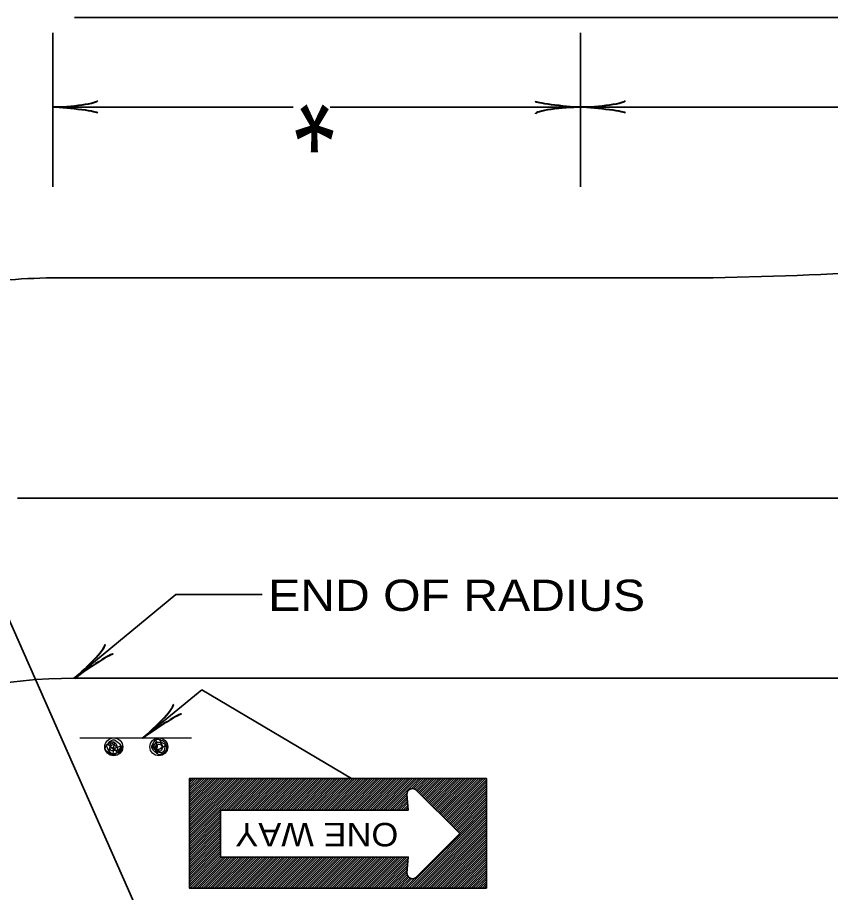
# Model space of a CAD drawing. Extents: x 1081 to 1936, y -630 to -24.
# Drawn here: x 1768.1 to 1830.4, y -254.8 to -187.6 of the extents above; entities that cross this region are included whole.
import ezdxf
from ezdxf.enums import TextEntityAlignment as Align

# ---------------------------------------------------------------- set-up
doc = ezdxf.new("R2010")
doc.units = 0
doc.layers.add('1', color=7, linetype='Continuous', lineweight=53)
doc.layers.add('4', color=7, linetype='Continuous', lineweight=25)

msp = doc.modelspace()

# ---------------------------------------------------------------- linework, layer by layer
at = {"layer": '1', "lineweight": 35}
for p, q in [((1772.44, -187.636), (1910.312, -187.636)), ((1770.768, -188.815), (1770.768, -200.637)), ((1811.244, -188.815), (1811.244, -200.637)), ((1789.206, -194.511), (1770.768, -194.511)), ((1811.244, -194.511), (1792.054, -194.511)), ((1892.659, -194.511), (1811.244, -194.511)), ((1754.117, -203.748), (1782.36, -267.638)), ((1771.98, -207.606), (1771.653, -207.606)), ((1821.432, -207.604), (1771.659, -207.604)), ((1826.968, -207.46), (1821.432, -207.604)), ((1772.978, -224.502), (1768.069, -224.502)), ((1910.312, -224.5), (1771.659, -224.5)), ((1780.221, -231.901), (1772.44, -238.324)), ((1780.221, -231.901), (1786.847, -231.901)), ((1772.44, -238.324), (1910.312, -238.324)), ((1782.205, -239.203), (1777.673, -242.919)), ((1782.205, -239.203), (1793.696, -246.024)), ((1785.974, -246.024), (1781.25, -250.749)), ((1785.805, -246.024), (1781.25, -250.579)), ((1785.635, -246.024), (1781.25, -250.409)), ((1785.465, -246.024), (1781.25, -250.239)), ((1785.296, -246.024), (1781.25, -250.07)), ((1785.126, -246.024), (1781.25, -249.9)), ((1784.956, -246.024), (1781.25, -249.73)), ((1784.786, -246.024), (1781.25, -249.561)), ((1784.617, -246.024), (1781.25, -249.391)), ((1784.447, -246.024), (1781.25, -249.221)), ((1784.277, -246.024), (1781.25, -249.052)), ((1784.108, -246.024), (1781.25, -248.882)), ((1783.938, -246.024), (1781.25, -248.712)), ((1783.768, -246.024), (1781.25, -248.542)), ((1783.599, -246.024), (1781.25, -248.373)), ((1783.429, -246.024), (1781.25, -248.203)), ((1783.259, -246.024), (1781.25, -248.033)), ((1783.089, -246.024), (1781.25, -247.864)), ((1782.92, -246.024), (1781.25, -247.694)), ((1782.75, -246.024), (1781.25, -247.524)), ((1782.58, -246.024), (1781.25, -247.354)), ((1782.411, -246.024), (1781.25, -247.185)), ((1782.241, -246.024), (1781.25, -247.015)), ((1782.071, -246.024), (1781.25, -246.845)), ((1781.901, -246.024), (1781.25, -246.676)), ((1781.732, -246.024), (1781.25, -246.506)), ((1781.562, -246.024), (1781.25, -246.336)), ((1781.392, -246.024), (1781.25, -246.167)), ((1786.144, -246.024), (1783.722, -248.446)), ((1786.314, -246.024), (1783.892, -248.446)), ((1786.484, -246.024), (1784.062, -248.446)), ((1786.653, -246.024), (1784.231, -248.446)), ((1786.823, -246.024), (1784.401, -248.446)), ((1786.993, -246.024), (1784.571, -248.446)), ((1787.162, -246.024), (1784.74, -248.446)), ((1787.332, -246.024), (1784.91, -248.446)), ((1787.502, -246.024), (1785.08, -248.446)), ((1787.671, -246.024), (1785.25, -248.446)), ((1787.841, -246.024), (1785.419, -248.446)), ((1788.011, -246.024), (1785.589, -248.446)), ((1788.181, -246.024), (1785.759, -248.446)), ((1788.35, -246.024), (1785.928, -248.446)), ((1788.52, -246.024), (1786.098, -248.446)), ((1788.69, -246.024), (1786.268, -248.446)), ((1788.859, -246.024), (1786.438, -248.446)), ((1789.029, -246.024), (1786.607, -248.446)), ((1789.199, -246.024), (1786.777, -248.446)), ((1789.369, -246.024), (1786.947, -248.446)), ((1789.538, -246.024), (1787.116, -248.446)), ((1789.708, -246.024), (1787.286, -248.446)), ((1789.878, -246.024), (1787.456, -248.446)), ((1790.047, -246.024), (1787.625, -248.446)), ((1790.217, -246.024), (1787.795, -248.446)), ((1790.387, -246.024), (1787.965, -248.446)), ((1790.556, -246.024), (1788.135, -248.446)), ((1790.726, -246.024), (1788.304, -248.446)), ((1790.896, -246.024), (1788.474, -248.446)), ((1791.066, -246.024), (1788.644, -248.446)), ((1791.235, -246.024), (1788.813, -248.446)), ((1791.405, -246.024), (1788.983, -248.446)), ((1791.575, -246.024), (1789.153, -248.446)), ((1791.744, -246.024), (1789.322, -248.446)), ((1791.914, -246.024), (1789.492, -248.446)), ((1792.084, -246.024), (1789.662, -248.446)), ((1792.254, -246.024), (1789.832, -248.446)), ((1792.423, -246.024), (1790.001, -248.446)), ((1792.593, -246.024), (1790.171, -248.446)), ((1792.763, -246.024), (1790.341, -248.446)), ((1792.932, -246.024), (1790.51, -248.446)), ((1793.102, -246.024), (1790.68, -248.446)), ((1793.272, -246.024), (1790.85, -248.446)), ((1793.441, -246.024), (1791.02, -248.446)), ((1793.611, -246.024), (1791.189, -248.446)), ((1793.781, -246.024), (1791.359, -248.446)), ((1793.951, -246.024), (1791.529, -248.446)), ((1794.12, -246.024), (1791.698, -248.446)), ((1794.29, -246.024), (1791.868, -248.446)), ((1794.46, -246.024), (1792.038, -248.446)), ((1794.629, -246.024), (1792.207, -248.446)), ((1794.799, -246.024), (1792.377, -248.446)), ((1794.969, -246.024), (1792.547, -248.446)), ((1795.139, -246.024), (1792.717, -248.446)), ((1795.308, -246.024), (1792.886, -248.446)), ((1795.478, -246.024), (1793.056, -248.446)), ((1795.648, -246.024), (1793.226, -248.446)), ((1795.817, -246.024), (1793.395, -248.446)), ((1795.987, -246.024), (1793.565, -248.446)), ((1796.157, -246.024), (1793.735, -248.446)), ((1796.326, -246.024), (1793.905, -248.446)), ((1796.496, -246.024), (1794.074, -248.446)), ((1796.666, -246.024), (1794.244, -248.446)), ((1796.836, -246.024), (1794.414, -248.446)), ((1797.005, -246.024), (1794.583, -248.446)), ((1797.175, -246.024), (1794.753, -248.446)), ((1797.345, -246.024), (1794.923, -248.446)), ((1797.514, -246.024), (1795.092, -248.446)), ((1797.684, -246.024), (1795.262, -248.446)), ((1797.854, -246.024), (1795.432, -248.446)), ((1798.024, -246.024), (1795.602, -248.446)), ((1798.193, -246.024), (1795.771, -248.446)), ((1798.363, -246.024), (1795.941, -248.446)), ((1798.533, -246.024), (1796.111, -248.446)), ((1798.702, -246.024), (1796.28, -248.446)), ((1798.872, -246.024), (1796.45, -248.446)), ((1799.042, -246.024), (1798.264, -246.802)), ((1799.211, -246.024), (1798.441, -246.795)), ((1799.381, -246.024), (1798.569, -246.837)), ((1799.551, -246.024), (1798.66, -246.916)), ((1799.721, -246.024), (1798.745, -247)), ((1799.89, -246.024), (1798.829, -247.085)), ((1800.06, -246.024), (1798.914, -247.17)), ((1800.23, -246.024), (1798.999, -247.255)), ((1800.399, -246.024), (1799.084, -247.34)), ((1800.569, -246.024), (1799.169, -247.425)), ((1800.739, -246.024), (1799.254, -247.509)), ((1800.909, -246.024), (1799.339, -247.594)), ((1801.078, -246.024), (1799.423, -247.679)), ((1801.248, -246.024), (1799.508, -247.764)), ((1801.418, -246.024), (1799.593, -247.849)), ((1801.587, -246.024), (1799.678, -247.934)), ((1801.757, -246.024), (1799.763, -248.019)), ((1801.927, -246.024), (1799.848, -248.103)), ((1802.096, -246.024), (1799.932, -248.188)), ((1802.266, -246.024), (1800.017, -248.273)), ((1802.436, -246.024), (1800.102, -248.358)), ((1802.606, -246.024), (1800.187, -248.443)), ((1802.775, -246.024), (1800.272, -248.528)), ((1802.945, -246.024), (1800.357, -248.613)), ((1803.115, -246.024), (1800.442, -248.697)), ((1803.284, -246.024), (1800.526, -248.782)), ((1803.454, -246.024), (1800.611, -248.867)), ((1803.624, -246.024), (1800.696, -248.952)), ((1803.793, -246.024), (1800.781, -249.037)), ((1803.963, -246.024), (1800.866, -249.122)), ((1804.05, -246.107), (1800.951, -249.207)), ((1804.05, -246.277), (1801.036, -249.291)), ((1798.596, -246.852), (1801.99, -250.246)), ((1804.05, -246.447), (1801.12, -249.376)), ((1804.05, -246.616), (1801.205, -249.461)), ((1804.05, -246.786), (1801.29, -249.546)), ((1804.05, -246.956), (1801.375, -249.631)), ((1797.947, -247.119), (1796.62, -248.446)), ((1797.938, -247.297), (1796.79, -248.446)), ((1797.952, -247.453), (1796.959, -248.446)), ((1797.966, -247.609), (1797.129, -248.446)), ((1804.05, -247.125), (1801.46, -249.716)), ((1804.05, -247.295), (1801.545, -249.8)), ((1804.05, -247.465), (1801.63, -249.885)), ((1804.05, -247.634), (1801.714, -249.97)), ((1797.979, -247.766), (1797.299, -248.446)), ((1797.993, -247.922), (1797.468, -248.446)), ((1798.007, -248.078), (1797.638, -248.446)), ((1798.02, -248.234), (1797.808, -248.446)), ((1804.05, -248.313), (1797.939, -254.424)), ((1804.05, -247.804), (1801.799, -250.055)), ((1804.05, -247.974), (1801.884, -250.14)), ((1804.05, -248.144), (1801.969, -250.225)), ((1783.639, -248.53), (1781.25, -250.918)), ((1783.639, -248.699), (1781.25, -251.088)), ((1783.639, -248.869), (1781.25, -251.258)), ((1783.639, -249.039), (1781.25, -251.427)), ((1798.034, -248.39), (1797.977, -248.446)), ((1804.05, -248.483), (1798.109, -254.424)), ((1804.05, -248.653), (1798.278, -254.424)), ((1804.05, -248.822), (1798.448, -254.424)), ((1804.05, -248.992), (1798.618, -254.424)), ((1783.639, -249.208), (1781.25, -251.597)), ((1783.639, -249.378), (1781.25, -251.767)), ((1783.639, -249.548), (1781.25, -251.937)), ((1804.05, -249.162), (1798.788, -254.424)), ((1804.05, -249.332), (1798.957, -254.424)), ((1804.05, -249.501), (1799.127, -254.424)), ((1804.05, -249.671), (1799.297, -254.424)), ((1783.639, -249.717), (1781.25, -252.106)), ((1783.639, -249.887), (1781.25, -252.276)), ((1783.639, -250.057), (1781.25, -252.446)), ((1783.639, -250.227), (1781.25, -252.615)), ((1801.99, -250.246), (1798.596, -253.64)), ((1804.05, -249.841), (1799.466, -254.424)), ((1804.05, -250.01), (1799.636, -254.424)), ((1804.05, -250.18), (1799.806, -254.424)), ((1804.05, -250.35), (1799.976, -254.424)), ((1783.639, -250.396), (1781.25, -252.785)), ((1783.639, -250.566), (1781.25, -252.955)), ((1783.639, -250.736), (1781.25, -253.124)), ((1783.639, -250.905), (1781.25, -253.294)), ((1804.05, -250.519), (1800.145, -254.424)), ((1804.05, -250.689), (1800.315, -254.424)), ((1804.05, -250.859), (1800.485, -254.424)), ((1804.05, -251.029), (1800.654, -254.424)), ((1783.639, -251.075), (1781.25, -253.464)), ((1783.639, -251.245), (1781.25, -253.634)), ((1783.639, -251.415), (1781.25, -253.803)), ((1783.639, -251.584), (1781.25, -253.973)), ((1804.05, -251.198), (1800.824, -254.424)), ((1804.05, -251.368), (1800.994, -254.424)), ((1804.05, -251.538), (1801.163, -254.424)), ((1804.05, -251.707), (1801.333, -254.424)), ((1783.639, -251.754), (1781.25, -254.143)), ((1783.639, -251.924), (1781.25, -254.312)), ((1783.686, -252.046), (1781.308, -254.424)), ((1783.856, -252.046), (1781.478, -254.424)), ((1784.025, -252.046), (1781.647, -254.424)), ((1784.195, -252.046), (1781.817, -254.424)), ((1784.365, -252.046), (1781.987, -254.424)), ((1784.534, -252.046), (1782.156, -254.424)), ((1784.704, -252.046), (1782.326, -254.424)), ((1784.874, -252.046), (1782.496, -254.424)), ((1785.044, -252.046), (1782.666, -254.424)), ((1785.213, -252.046), (1782.835, -254.424)), ((1785.383, -252.046), (1783.005, -254.424)), ((1785.553, -252.046), (1783.175, -254.424)), ((1785.723, -252.046), (1783.344, -254.424)), ((1785.892, -252.046), (1783.514, -254.424)), ((1786.062, -252.046), (1783.684, -254.424)), ((1786.232, -252.046), (1783.854, -254.424)), ((1786.401, -252.046), (1784.023, -254.424)), ((1786.571, -252.046), (1784.193, -254.424)), ((1786.741, -252.046), (1784.363, -254.424)), ((1786.91, -252.046), (1784.532, -254.424)), ((1787.08, -252.046), (1784.702, -254.424)), ((1787.25, -252.046), (1784.872, -254.424)), ((1787.42, -252.046), (1785.041, -254.424)), ((1787.589, -252.046), (1785.211, -254.424)), ((1787.759, -252.046), (1785.381, -254.424)), ((1787.929, -252.046), (1785.551, -254.424)), ((1788.098, -252.046), (1785.72, -254.424)), ((1788.268, -252.046), (1785.89, -254.424)), ((1788.438, -252.046), (1786.06, -254.424)), ((1788.607, -252.046), (1786.229, -254.424)), ((1788.777, -252.046), (1786.399, -254.424)), ((1788.947, -252.046), (1786.569, -254.424)), ((1789.117, -252.046), (1786.739, -254.424)), ((1789.286, -252.046), (1786.908, -254.424)), ((1789.456, -252.046), (1787.078, -254.424)), ((1789.626, -252.046), (1787.248, -254.424)), ((1789.795, -252.046), (1787.417, -254.424)), ((1789.965, -252.046), (1787.587, -254.424)), ((1790.135, -252.046), (1787.757, -254.424)), ((1790.305, -252.046), (1787.926, -254.424)), ((1790.474, -252.046), (1788.096, -254.424)), ((1790.644, -252.046), (1788.266, -254.424)), ((1790.814, -252.046), (1788.436, -254.424)), ((1790.983, -252.046), (1788.605, -254.424)), ((1791.153, -252.046), (1788.775, -254.424)), ((1791.323, -252.046), (1788.945, -254.424)), ((1791.492, -252.046), (1789.114, -254.424)), ((1791.662, -252.046), (1789.284, -254.424)), ((1791.832, -252.046), (1789.454, -254.424)), ((1792.002, -252.046), (1789.624, -254.424)), ((1792.171, -252.046), (1789.793, -254.424)), ((1792.341, -252.046), (1789.963, -254.424)), ((1792.511, -252.046), (1790.133, -254.424)), ((1792.68, -252.046), (1790.302, -254.424)), ((1792.85, -252.046), (1790.472, -254.424)), ((1793.02, -252.046), (1790.642, -254.424)), ((1793.19, -252.046), (1790.811, -254.424)), ((1793.359, -252.046), (1790.981, -254.424)), ((1793.529, -252.046), (1791.151, -254.424)), ((1793.699, -252.046), (1791.321, -254.424)), ((1793.868, -252.046), (1791.49, -254.424)), ((1794.038, -252.046), (1791.66, -254.424)), ((1794.208, -252.046), (1791.83, -254.424)), ((1794.377, -252.046), (1791.999, -254.424)), ((1794.547, -252.046), (1792.169, -254.424)), ((1794.717, -252.046), (1792.339, -254.424)), ((1794.887, -252.046), (1792.509, -254.424)), ((1795.056, -252.046), (1792.678, -254.424)), ((1795.226, -252.046), (1792.848, -254.424)), ((1795.396, -252.046), (1793.018, -254.424)), ((1795.565, -252.046), (1793.187, -254.424)), ((1795.735, -252.046), (1793.357, -254.424)), ((1795.905, -252.046), (1793.527, -254.424)), ((1796.075, -252.046), (1793.696, -254.424)), ((1796.244, -252.046), (1793.866, -254.424)), ((1796.414, -252.046), (1794.036, -254.424)), ((1796.584, -252.046), (1794.206, -254.424)), ((1796.753, -252.046), (1794.375, -254.424)), ((1796.923, -252.046), (1794.545, -254.424)), ((1797.093, -252.046), (1794.715, -254.424)), ((1797.262, -252.046), (1794.884, -254.424)), ((1797.432, -252.046), (1795.054, -254.424)), ((1797.602, -252.046), (1795.224, -254.424)), ((1797.772, -252.046), (1795.394, -254.424)), ((1797.941, -252.046), (1795.563, -254.424)), ((1798.032, -252.125), (1795.733, -254.424)), ((1798.016, -252.311), (1795.903, -254.424)), ((1804.05, -251.877), (1801.503, -254.424)), ((1804.05, -252.047), (1801.673, -254.424)), ((1804.05, -252.217), (1801.842, -254.424)), ((1804.05, -252.386), (1802.012, -254.424)), ((1797.999, -252.497), (1796.072, -254.424)), ((1797.983, -252.683), (1796.242, -254.424)), ((1797.967, -252.869), (1796.412, -254.424)), ((1797.951, -253.055), (1796.581, -254.424)), ((1804.05, -252.556), (1802.182, -254.424)), ((1804.05, -252.726), (1802.351, -254.424)), ((1804.05, -252.895), (1802.521, -254.424)), ((1804.05, -253.065), (1802.691, -254.424)), ((1797.934, -253.241), (1796.751, -254.424)), ((1797.953, -253.393), (1796.921, -254.424)), ((1798.007, -253.508), (1797.091, -254.424)), ((1798.086, -253.599), (1797.26, -254.424)), ((1798.19, -253.664), (1797.43, -254.424)), ((1798.323, -253.701), (1797.6, -254.424)), ((1798.515, -253.679), (1797.769, -254.424)), ((1804.05, -253.235), (1802.861, -254.424)), ((1804.05, -253.404), (1803.03, -254.424)), ((1804.05, -253.574), (1803.2, -254.424)), ((1804.05, -253.744), (1803.37, -254.424)), ((1804.05, -253.913), (1803.539, -254.424)), ((1804.05, -254.083), (1803.709, -254.424)), ((1804.05, -254.253), (1803.879, -254.424)), ((1804.05, -254.423), (1804.048, -254.424))]:
    msp.add_line(p, q, dxfattribs=at)
at = {"layer": '1', "lineweight": 25}
msp.add_line((1781.42, -242.929), (1772.852, -242.929), dxfattribs=at)
at = {"layer": '1', "lineweight": 35}
msp.add_lwpolyline([(1804.05, -254.424), (1781.25, -254.424), (1781.25, -246.024), (1804.05, -246.024)], close=True, dxfattribs=at)
msp.add_lwpolyline([(1797.934, -253.242), (1798.039, -252.046), (1783.639, -252.046), (1783.639, -248.446), (1798.039, -248.446), (1797.934, -247.251)], dxfattribs=at)
for centre, radius, start, end in [((1771.569, -263.623), 56.019, 89.90832, 97.57279), ((1772.44, -276.723), 38.4, 90, 180), ((1798.37, -247.225), 0.436, 58.76645, 183.36449), ((1798.37, -253.267), 0.436, 176.63551, 301.23355)]:
    msp.add_arc(centre, radius, start, end, dxfattribs=at)
at = {"layer": '1', "lineweight": 40}
for centre, major_axis, ratio, start_param, end_param in [((1772.077, -194.18), (-2.143, -0.187), 0.122415, 0.896353, 3.141593), ((1772.077, -194.18), (-2.143, -0.187), 0.122415, 0.896353, 3.141593), ((1812.554, -194.18), (-2.143, -0.187), 0.122415, 0.896353, 3.141593), ((1772.112, -194.765), (-2.108, 0.211), 0.07063, 3.140715, 5.41811), ((1772.112, -194.765), (-2.108, 0.211), 0.07063, 3.140715, 5.41811), ((1809.935, -194.843), (2.143, 0.187), 0.122415, 0.896353, 3.141593), ((1809.9, -194.257), (2.108, -0.211), 0.07063, 3.140715, 5.41811), ((1812.589, -194.765), (-2.108, 0.211), 0.07063, 3.140715, 5.41811), ((1773.239, -237.235), (-1.533, -1.509), 0.122415, 0.896353, 3.141593), ((1773.239, -237.235), (-1.533, -1.509), 0.122415, 0.896353, 3.141593), ((1773.638, -237.664), (-1.76, -1.179), 0.07063, 3.140715, 5.41811), ((1773.638, -237.664), (-1.76, -1.179), 0.07063, 3.140715, 5.41811), ((1778.476, -241.833), (-1.538, -1.504), 0.122415, 0.896353, 3.141593), ((1778.874, -242.263), (1.763, 1.174), 0.07063, 6.282307, 8.559703)]:
    msp.add_ellipse(centre, major_axis=major_axis, ratio=ratio, start_param=start_param, end_param=end_param, dxfattribs=at)
at = {"layer": '1', "lineweight": 35}
msp.add_spline([(1880.184, -201.652), (1858.232, -203.332), (1841.432, -206.404), (1826.968, -207.46)], degree=3, dxfattribs=at)
at = {"layer": '1', "lineweight": 25}
for points in [[(1778.9, -242.996), (1779.27, -243.164), (1779.505, -243.533), (1779.438, -243.937), (1779.001, -244.205), (1778.598, -243.97), (1778.363, -243.634), (1778.43, -243.399), (1778.9, -242.996), (1779.136, -243.264), (1779.337, -243.365), (1779.371, -243.567), (1779.136, -244.037), (1778.9, -244.004), (1778.732, -243.869), (1778.464, -243.701), (1778.665, -243.298), (1778.934, -243.231), (1779.102, -243.365), (1779.203, -243.567), (1779.136, -243.769), (1779.068, -243.903), (1778.732, -243.802), (1778.8, -243.567), (1778.8, -243.433), (1779.068, -243.433), (1779.136, -243.634), (1778.766, -243.769), (1778.699, -243.735), (1778.396, -243.433), (1778.833, -244.071), (1778.732, -243.769), (1779.236, -244.105), (1779.472, -243.533), (1778.766, -243.769), (1778.732, -243.164), (1778.632, -243.298), (1778.766, -243.769)], [(1775.507, -243.063), (1775.843, -243.298), (1776.011, -243.634), (1775.91, -243.869), (1775.54, -244.105), (1775.171, -244.105), (1774.801, -243.735), (1775.036, -243.298), (1775.507, -243.063), (1775.708, -243.197), (1775.876, -243.298), (1775.944, -243.601), (1775.708, -244.004), (1775.574, -244.172), (1775.104, -243.903), (1775.171, -243.567), (1775.238, -243.365), (1775.372, -243.298), (1775.574, -243.298), (1775.675, -243.5), (1775.708, -243.869), (1775.473, -243.869), (1775.305, -243.903), (1775.171, -243.701), (1775.406, -243.399), (1775.608, -243.533), (1775.641, -243.668), (1775.406, -243.701), (1775.44, -243.769), (1774.936, -243.399), (1775.372, -244.205), (1775.473, -243.735), (1775.776, -244.037), (1776.112, -243.567), (1775.406, -243.701), (1775.54, -243.264), (1775.07, -243.365), (1775.406, -243.701)]]:
    msp.add_spline(points, degree=3, dxfattribs=at)
at = {"layer": '4'}
for centre in [(1775.453, -243.59), (1778.908, -243.589)]:
    msp.add_circle(centre, 0.689, dxfattribs=at)

# ---------------------------------------------------------------- texts
at = {"layer": '1'}
for s, height, width, p in [('*', 7.2, 0.85, (1790.847, -190.77)), ('ONE WAY', 1.8, 1.1, (1791.022, -249.423))]:
    msp.add_text(s, height=height, rotation=180, dxfattribs=dict(at, width=width)).set_placement(p, align=Align.CENTER)
at = {"layer": '1', "width": 1.15}
msp.add_text('END OF RADIUS', height=2.4, dxfattribs=at).set_placement((1801.751, -233.161), align=Align.CENTER)

doc.saveas('drawing.dxf')
